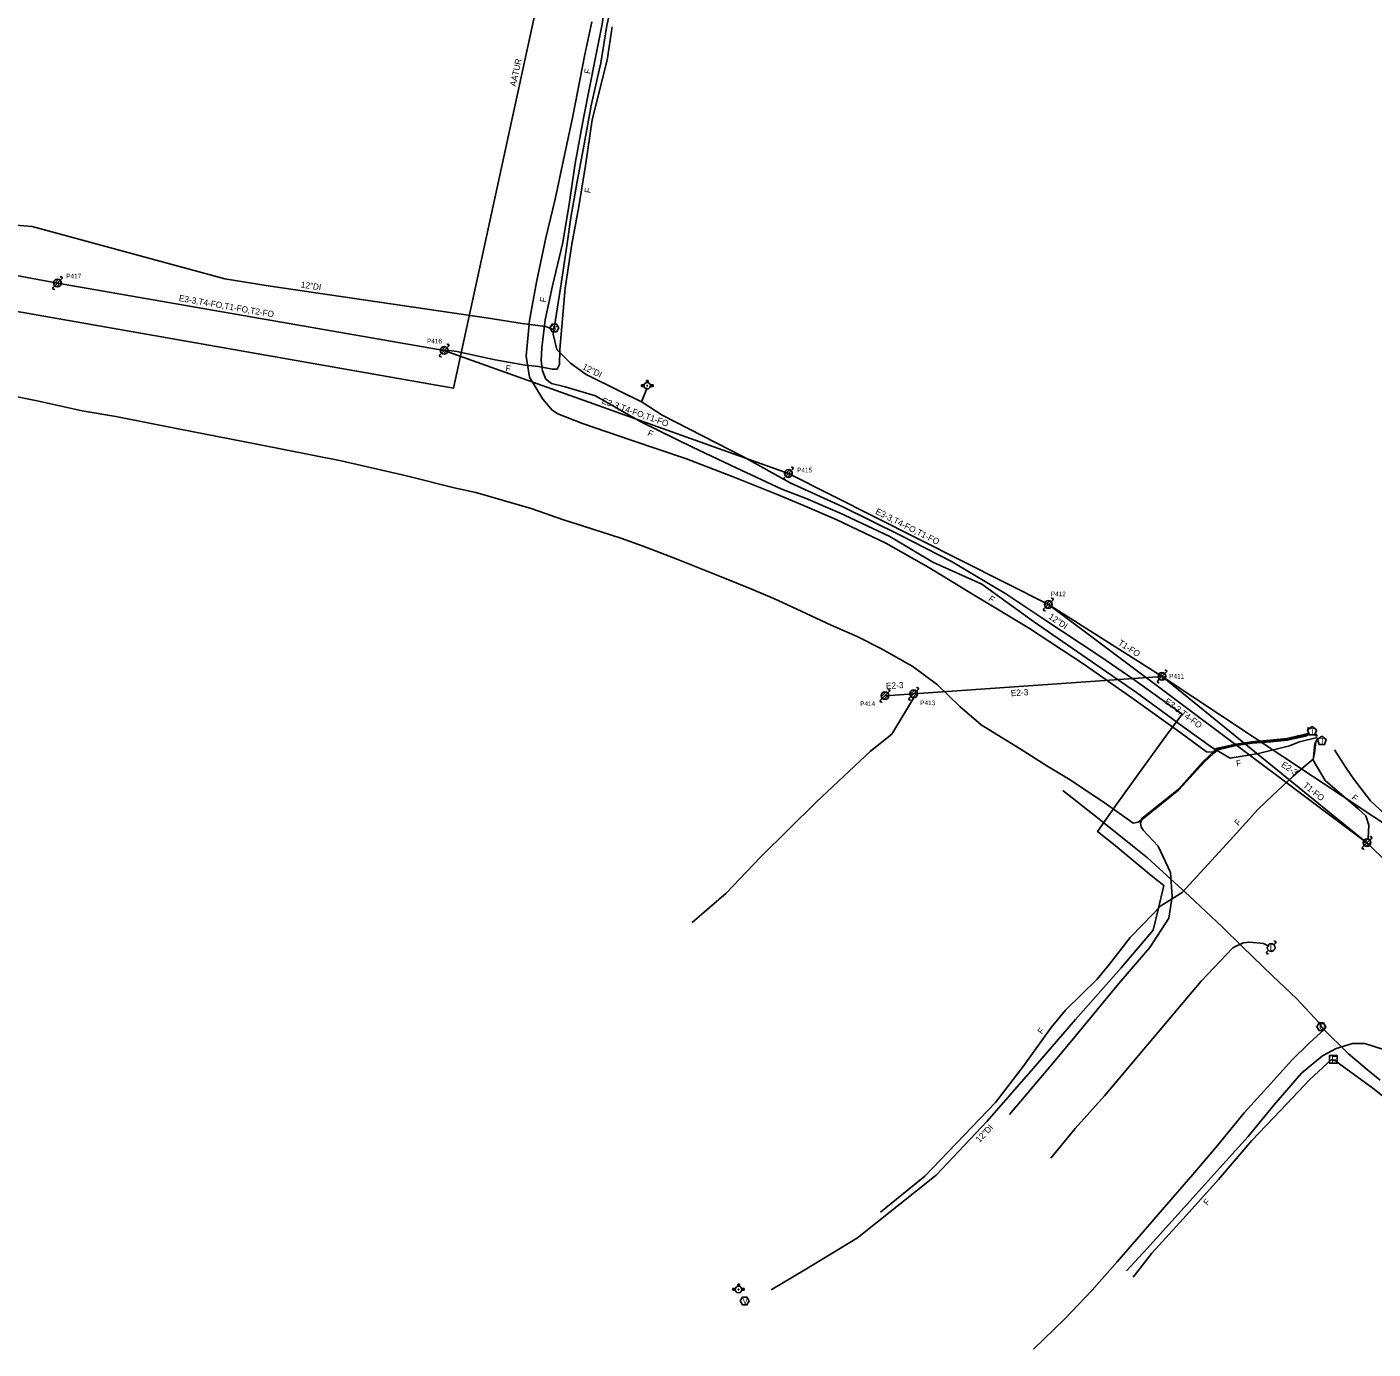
# Model space of a CAD drawing. Extents: x 1614474 to 1865144, y 1098877 to 1212550.
# Drawn here: x 1819688 to 1820556, y 1191145 to 1191998 of the extents above; entities that cross this region are included whole.
import ezdxf

# ---------------------------------------------------------------- set-up
doc = ezdxf.new("R2010")
doc.units = 0
for name, color, linetype in [('RD_EX_SU_Elec', 7, 'Continuous'), ('RD_EX_SU_Gas', 7, 'Continuous'), ('RD_EX_SU_H2O', 7, 'Continuous'), ('RD_EX_SU_Ovhd', 7, 'Continuous'), ('RD_EX_SU_Pole', 7, 'Continuous'), ('RD_EX_SU_Telecom', 7, 'Continuous'), ('RD_EX_SU_TX_H2O', 7, 'Continuous'), ('RD_EX_SU_TX_Pole', 7, 'Continuous'), ('RD_EX_SU_TX_Telecom', 7, 'Continuous')]:
    doc.layers.add(name, color=color, linetype=linetype)

# ---------------------------------------------------------------- blocks, each defined once
blk = doc.blocks.new('SUE_WV')
at = {"layer": 'RD_EX_SU_H2O'}
blk.add_lwpolyline([(2.89, 0), (1.44, 2.5), (-1.44, 2.5), (-2.89, 0), (-1.44, -2.5), (1.44, -2.5)], close=True, dxfattribs=at)
blk.add_text('V', height=3.75, dxfattribs=at).set_placement((-1.43, -1.88))
blk = doc.blocks.new('SUE_WFH')
at = {"layer": 'RD_EX_SU_H2O'}
for p, q in [((-2.01, 0.6), (-3.65, 0.6)), ((-3.65, 0.6), (-3.65, -0.45)), ((-0.48, 3.38), (-0.48, 2.04)), ((0.57, 3.38), (-0.48, 3.38)), ((0.57, 2.02), (0.57, 3.38)), ((3.7, 0.6), (2.01, 0.6)), ((3.7, -0.45), (3.7, 0.6)), ((-3.65, -0.45), (-2.05, -0.45)), ((2.05, -0.45), (3.7, -0.45))]:
    blk.add_line(p, q, dxfattribs=at)
for radius in [2.1, 0.263]:
    blk.add_circle((0, 0), radius, dxfattribs=at)
for start, end in [(163.3387, 192.31502), (74.24552, 103.21276), (347.68498, 16.6613)]:
    blk.add_arc((0, 0), 2.1, start, end, dxfattribs=at)
blk = doc.blocks.new('SUE_GVC')
at = {"layer": 'RD_EX_SU_Gas'}
blk.add_lwpolyline([(1.44, -2.5), (2.89, 0), (1.44, 2.5), (-1.44, 2.5), (-2.89, 0), (-1.44, -2.5)], close=True, dxfattribs=at)
blk.add_text('G', height=3.75, dxfattribs=at).set_placement((-1.34, -1.88))
blk = doc.blocks.new('SUE_PP')
at = {"layer": 'RD_EX_SU_Pole'}
for p, q in [((-2.41, -0.65), (0.65, 2.41)), ((-1.77, -1.77), (1.77, 1.77)), ((-0.65, -2.41), (2.41, 0.65)), ((1.77, 1.77), (2.83, 2.83)), ((-2.83, -2.83), (-1.77, -1.77))]:
    blk.add_line(p, q, dxfattribs=at)
blk.add_circle((0, 0), 2.5, dxfattribs=at)
for centre, start, end in [((2.3, 3.36), 315, 135), ((-2.3, -3.36), 135, 315)]:
    blk.add_arc(centre, 0.75, start, end, dxfattribs=at)

msp = doc.modelspace()

# ---------------------------------------------------------------- linework, layer by layer
at = {"layer": 'RD_EX_SU_Elec'}
for points in [[(1820117.23, 1191420.46), (1820139.16, 1191439.31), (1820161.2, 1191462.5), (1820197.42, 1191498.27), (1820232.28, 1191530.9), (1820245.99, 1191541.84), (1820260.6, 1191566.08)], [(1820531.48, 1191531.69), (1820539.33, 1191519.78), (1820543.95, 1191512.8), (1820554.72, 1191498.92), (1820566.71, 1191487.66), (1820596, 1191467.52), (1820611.35, 1191452.66)], [(1820348.6, 1191268.45), (1820364.31, 1191287.4), (1820383.23, 1191308.59), (1820445.62, 1191382.43), (1820465.97, 1191404.13), (1820472.71, 1191407.24), (1820476.96, 1191407.7), (1820485.75, 1191406.82), (1820489.35, 1191404.99)], [(1820397.44, 1191195.65), (1820410.78, 1191210.12), (1820430.67, 1191232.22), (1820453.54, 1191257.69), (1820475.8, 1191282.25), (1820492.44, 1191302.57), (1820510.32, 1191323.24), (1820523.78, 1191334.32), (1820532.63, 1191339.18), (1820543.19, 1191342.42), (1820551.02, 1191342.27), (1820563.15, 1191338.5)]]:
    msp.add_lwpolyline(points, dxfattribs=at)
at = {"layer": 'RD_EX_SU_Gas'}
for points in [[(1820356.38, 1191505.62), (1820378.54, 1191488.19), (1820401.21, 1191469.89), (1820410.93, 1191462.17), (1820423.3, 1191450.65), (1820438.07, 1191437.28), (1820459.18, 1191417.57), (1820472.14, 1191404.77), (1820491.57, 1191386.07), (1820507.34, 1191371.1), (1820521.32, 1191356.1), (1820522.41, 1191354.63), (1820522.99, 1191353.17), (1820524.24, 1191351.86), (1820540.44, 1191335.88), (1820552.74, 1191325.4), (1820560.89, 1191318.77)], [(1820337.37, 1191145.2), (1820357.64, 1191164.75), (1820375.15, 1191183.24), (1820391.38, 1191201.45), (1820406.75, 1191219.39), (1820421.97, 1191236.64), (1820440.08, 1191257.73), (1820456.04, 1191276.44), (1820473.33, 1191297.51), (1820490.48, 1191316.43), (1820503.99, 1191331.57), (1820515.23, 1191342.64), (1820524.79, 1191351.32)]]:
    msp.add_lwpolyline(points, dxfattribs=at)
at = {"layer": 'RD_EX_SU_H2O'}
msp.add_line((1820084.49, 1191756.32), (1820088.16, 1191765.33), dxfattribs=at)
for points in [[(1820036.51, 1191858.44), (1820038.88, 1191875.15), (1820042.84, 1191897.15), (1820047.53, 1191922.47), (1820051.99, 1191947.48), (1820058.18, 1191974.95), (1820062.15, 1191999.04), (1820067.98, 1192024.17), (1820071.51, 1192043.35), (1820077.48, 1192067.06), (1820084.61, 1192099.31), (1820091.86, 1192124.8), (1820100.41, 1192152.47), (1820104.82, 1192168.52), (1820107.91, 1192178.54)], [(1819147.33, 1191918.52), (1819544.16, 1191883.35), (1819570.61, 1191880.2), (1819605.16, 1191876.28), (1819691.46, 1191869.4), (1819815.73, 1191835.67), (1819843.7, 1191831.09), (1819985.82, 1191810.12), (1820007.46, 1191806.84)], [(1820036.51, 1191858.44), (1820032.74, 1191832.48), (1820028.36, 1191805.11), (1820027.56, 1191799.88), (1820029.89, 1191789.99), (1820038.66, 1191781.17), (1820048.91, 1191773.83), (1820071.03, 1191762.91), (1820084.99, 1191756.08), (1820097.9, 1191747.71), (1820149.94, 1191721.05)], [(1820007.46, 1191806.84), (1820022.65, 1191804.77), (1820028.04, 1191803.02)], [(1820149.94, 1191721.05), (1820180.51, 1191704), (1820213.96, 1191688.84), (1820251.31, 1191670.31), (1820284.92, 1191653.1), (1820319.56, 1191632.41)], [(1820168.21, 1191183.47), (1820189.95, 1191196.34), (1820223.8, 1191217), (1820274.56, 1191257.42), (1820307.56, 1191292.16), (1820337.07, 1191326.17), (1820364.43, 1191357.7), (1820393.91, 1191391.11), (1820414.48, 1191415.4), (1820417.89, 1191428.69), (1820421.41, 1191444.22), (1820413.31, 1191450.68), (1820390.01, 1191470.08), (1820378.66, 1191479.03), (1820391.29, 1191497.09), (1820406.78, 1191518.65), (1820423.16, 1191541.13), (1820433.19, 1191554.81), (1820401.46, 1191577.53), (1820380.81, 1191591.84), (1820342.7, 1191616.89), (1820319.56, 1191632.41)]]:
    msp.add_lwpolyline(points, dxfattribs=at)
at = {"layer": 'RD_EX_SU_Ovhd'}
for p, q in [((1819457.3, 1191879.55), (1819707.8, 1191832.9)), ((1819707.8, 1191832.9), (1819957.27, 1191789.42)), ((1819957.27, 1191789.42), (1820179.31, 1191710.02)), ((1820179.31, 1191710.02), (1820346.97, 1191625.54)), ((1820346.97, 1191625.54), (1820420.31, 1191579.15)), ((1820346.97, 1191625.54), (1820552.49, 1191471.84)), ((1820260.11, 1191567.92), (1820420.31, 1191579.15)), ((1820420.31, 1191579.15), (1820611.99, 1191452.04)), ((1820420.31, 1191579.15), (1820552.49, 1191471.84)), ((1820241.59, 1191566.68), (1820260.11, 1191567.92)), ((1820552.49, 1191471.84), (1820734.07, 1191296.93))]:
    msp.add_line(p, q, dxfattribs=at)
at = {"layer": 'RD_EX_SU_Pole'}
for p, q in [((1819705.38, 1191832.25), (1819708.44, 1191835.31)), ((1819706.03, 1191831.13), (1819709.57, 1191834.66)), ((1819707.15, 1191830.48), (1819710.21, 1191833.54)), ((1819709.57, 1191834.66), (1819710.63, 1191835.72)), ((1819704.97, 1191830.07), (1819706.03, 1191831.13)), ((1819954.86, 1191788.78), (1819957.92, 1191791.84)), ((1819955.51, 1191787.66), (1819959.04, 1191791.19)), ((1819956.63, 1191787.01), (1819959.69, 1191790.07)), ((1819959.04, 1191791.19), (1819960.1, 1191792.25)), ((1819954.45, 1191786.6), (1819955.51, 1191787.66)), ((1820176.9, 1191709.37), (1820179.96, 1191712.43)), ((1820177.54, 1191708.25), (1820181.08, 1191711.78)), ((1820181.08, 1191711.78), (1820182.14, 1191712.85)), ((1820176.48, 1191707.19), (1820177.54, 1191708.25)), ((1820178.66, 1191707.6), (1820181.73, 1191710.66)), ((1820344.56, 1191624.89), (1820347.62, 1191627.96)), ((1820345.2, 1191623.77), (1820348.74, 1191627.31)), ((1820346.32, 1191623.13), (1820349.39, 1191626.19)), ((1820348.74, 1191627.31), (1820349.8, 1191628.37)), ((1820344.14, 1191622.71), (1820345.2, 1191623.77)), ((1820487.84, 1191401.39), (1820488.9, 1191402.45)), ((1820492.44, 1191405.99), (1820493.5, 1191407.05))]:
    msp.add_line(p, q, dxfattribs=at)
for centre in [(1819707.8, 1191832.9), (1819957.27, 1191789.42), (1820179.31, 1191710.02), (1820346.97, 1191625.54), (1820490.67, 1191404.22)]:
    msp.add_circle(centre, 2.5, dxfattribs=at)
for centre, start, end in [((1819710.1, 1191836.25), 315, 135), ((1819705.5, 1191829.54), 135, 315), ((1819959.57, 1191792.78), 315, 135), ((1819954.98, 1191786.07), 135, 315), ((1820181.61, 1191713.38), 315, 135), ((1820177.01, 1191706.66), 135, 315), ((1820349.27, 1191628.9), 315, 135), ((1820344.67, 1191622.18), 135, 315), ((1820492.97, 1191407.58), 315, 135), ((1820488.37, 1191400.86), 135, 315)]:
    msp.add_arc(centre, 0.75, start, end, dxfattribs=at)
at = {"layer": 'RD_EX_SU_Telecom'}
for p, q in [((1820515.43, 1191545.4), (1820514.02, 1191546.18)), ((1820520.17, 1191540.43), (1820518.6, 1191542.22)), ((1820520.58, 1191541.05), (1820518.99, 1191542.6))]:
    msp.add_line(p, q, dxfattribs=at)
for points in [[(1820020.74, 1191776.2), (1820019.8, 1191782.68), (1820020.22, 1191791.05), (1820022.34, 1191809.12), (1820027.11, 1191831.03), (1820033.7, 1191858.96), (1820037.9, 1191883.86), (1820041.76, 1191910.02), (1820047.2, 1191939.2), (1820054.87, 1191978.46), (1820059.17, 1191999.94), (1820062.87, 1192025.73), (1820073.1, 1192071.26), (1820081.89, 1192097.42), (1820088.82, 1192119.73), (1820093.94, 1192134.6), (1820093.61, 1192137.35)], [(1819273.38, 1191837.73), (1819283.19, 1191836.01), (1819404.71, 1191814.63), (1819438.76, 1191858.18), (1819652.24, 1191819.72), (1819963.17, 1191765.03), (1820039.32, 1192115.22)], [(1819958.67, 1191789.48), (1819965.36, 1191788.65), (1819990.11, 1191783.39), (1820009.52, 1191779.93), (1820017.99, 1191779.05), (1820027.08, 1191777.25), (1820030.13, 1191777.34), (1820031.66, 1191780.35), (1820031.76, 1191790.12), (1820035.32, 1191829.6), (1820039.63, 1191857.97), (1820044.11, 1191882.32), (1820048.45, 1191908.69), (1820052.7, 1191938.14), (1820062.38, 1191976.64), (1820065.5, 1191998.17)], [(1820052.52, 1192001.38), (1820047.98, 1191980.33), (1820040.32, 1191940.51), (1820034.15, 1191912.36), (1820028.82, 1191886.96), (1820022.84, 1191862.03), (1820016.86, 1191833.55), (1820012.35, 1191808.75), (1820010.12, 1191785.81), (1820012.35, 1191772.27), (1820020.8, 1191757.93), (1820026.83, 1191750.92), (1820030.64, 1191748.54), (1820046.44, 1191742.31), (1820077.94, 1191731.42), (1820113.63, 1191719.54), (1820143.66, 1191707.77), (1820171.58, 1191696.66), (1820188.52, 1191689.49), (1820210, 1191680.26), (1820242.07, 1191664.99), (1820269.85, 1191649.36), (1820299.09, 1191631.62), (1820334.25, 1191610.38), (1820369.19, 1191587.42), (1820400.75, 1191565.28), (1820431.84, 1191543.08), (1820449.03, 1191530.43), (1820453.13, 1191530.22), (1820455.98, 1191532.12), (1820467.77, 1191534.98), (1820478.15, 1191536.64), (1820490.18, 1191537.63), (1820501.2, 1191538.42), (1820508.29, 1191540.19), (1820512.2, 1191541.13), (1820515.79, 1191541.49)], [(1820020.74, 1191776.2), (1820022.71, 1191770.94), (1820026.37, 1191767.99), (1820035.29, 1191765.91), (1820054.91, 1191760.12), (1820084.1, 1191743.35), (1820117.42, 1191727.04), (1820145.61, 1191713.71), (1820175.13, 1191699.84), (1820190.65, 1191693.83), (1820212.32, 1191684.58), (1820244.72, 1191669.28), (1820272.34, 1191652.9), (1820304, 1191638.56), (1820337.46, 1191614.55), (1820371.94, 1191590.6), (1820403.73, 1191568.67), (1820434.6, 1191546.1), (1820452.9, 1191533.04), (1820464.31, 1191526.31), (1820482.47, 1191529.49), (1820502.47, 1191534.41), (1820508.98, 1191537.02), (1820520.46, 1191539.72)], [(1819660.43, 1191763.87), (1819694.61, 1191757), (1819723.82, 1191750.41), (1819745.33, 1191746.78), (1819785.74, 1191738.86), (1819836.47, 1191728.92), (1819890.68, 1191718.19), (1819932.98, 1191708.44), (1819963.61, 1191700.84), (1819977.57, 1191697.72), (1820013.32, 1191687.36), (1820034.25, 1191680.18), (1820047.2, 1191676.14), (1820071.22, 1191668.31), (1820085.62, 1191663.05), (1820107.91, 1191654.46), (1820138.02, 1191642.53), (1820154.97, 1191635.7), (1820169.94, 1191629.34), (1820187.52, 1191621.32), (1820206.84, 1191612.24), (1820223.58, 1191604.85), (1820239.3, 1191596.93), (1820259.59, 1191585.43), (1820275.52, 1191573.64), (1820289.75, 1191559.63), (1820303.72, 1191547.89), (1820316.47, 1191540.02), (1820328.82, 1191532.49), (1820346.06, 1191521.42), (1820360.98, 1191512.34), (1820384.54, 1191496.63), (1820397.71, 1191487.24), (1820401.7, 1191484.54), (1820404.85, 1191485.1), (1820407.62, 1191487.09), (1820431.12, 1191505.96), (1820447.36, 1191523.8), (1820453.79, 1191529.53), (1820456.32, 1191531.7), (1820467.89, 1191534.55), (1820478.36, 1191536.17), (1820490.4, 1191536.86), (1820501.23, 1191538.05), (1820508.84, 1191539.7), (1820512.73, 1191540.48), (1820515.71, 1191542.39)], [(1820238.66, 1191233.45), (1820267.28, 1191256.68), (1820312.78, 1191304.24), (1820330.7, 1191327.52), (1820348.67, 1191352.59), (1820358.07, 1191363.8), (1820378.51, 1191383.93), (1820386.44, 1191393.42), (1820399.66, 1191410.8), (1820407.85, 1191419.06), (1820419.53, 1191431.12), (1820433.26, 1191439.81), (1820457.16, 1191465.69), (1820466.35, 1191475.93), (1820482.26, 1191493.4), (1820491.49, 1191502.37), (1820504.62, 1191514.58), (1820511.38, 1191520.35), (1820517.86, 1191525.75), (1820518.74, 1191529.64), (1820519.45, 1191536.87), (1820520.97, 1191539.38)], [(1820321.86, 1191296.54), (1820349.08, 1191328.64), (1820362.02, 1191344.28), (1820375.13, 1191360.15), (1820392.5, 1191381.01), (1820412.42, 1191404.19), (1820424.71, 1191423.27), (1820426.91, 1191437.06), (1820425.78, 1191452.64), (1820417.72, 1191469.72), (1820408.02, 1191480), (1820406.75, 1191482.1), (1820406.36, 1191484.51), (1820407.15, 1191487.46), (1820430.84, 1191506.36), (1820446.77, 1191524.27), (1820454.01, 1191531), (1820455.24, 1191532.59), (1820467.85, 1191535.42), (1820478.17, 1191537.02), (1820490.11, 1191537.99), (1820501.02, 1191539.06), (1820508.02, 1191540.9), (1820512.16, 1191541.59), (1820514.57, 1191542.37)], [(1820520.54, 1191538.8), (1820518.75, 1191535.73), (1820517.8, 1191525), (1820525.47, 1191511.91), (1820546.73, 1191493.75), (1820551.66, 1191489.29), (1820551.74, 1191489.21), (1820553.72, 1191483.12), (1820553.33, 1191474.7)], [(1820401.64, 1191191.64), (1820413.7, 1191207.1), (1820433.83, 1191229.18), (1820456.81, 1191254.54), (1820478.18, 1191279.82), (1820496.67, 1191299.09), (1820515.59, 1191319.16), (1820529.42, 1191331.83), (1820532.45, 1191331.17), (1820534.97, 1191328.91), (1820548.22, 1191319.22), (1820556.16, 1191313.41), (1820569.93, 1191302.49)]]:
    msp.add_lwpolyline(points, dxfattribs=at)
for points in [[(1820517.03, 1191546.79), (1820514.17, 1191544.72), (1820515.26, 1191541.36), (1820518.79, 1191541.36), (1820519.88, 1191544.72)], [(1820523.36, 1191540.55), (1820520.51, 1191538.47), (1820521.6, 1191535.12), (1820525.12, 1191535.12), (1820526.21, 1191538.47)], [(1820533.32, 1191334.53), (1820528.32, 1191334.53), (1820528.32, 1191329.53), (1820533.32, 1191329.53)]]:
    msp.add_lwpolyline(points, close=True, dxfattribs=at)

# ---------------------------------------------------------------- block references
at = {"layer": 'RD_EX_SU_Gas'}
msp.add_blockref('SUE_GVC', (1820522.99, 1191353.17), dxfattribs=at)
at = {"layer": 'RD_EX_SU_H2O'}
for name, p in [('SUE_WV', (1820028.27, 1191803.96)), ('SUE_WFH', (1820088.25, 1191766.67)), ('SUE_WFH', (1820147.09, 1191183.66)), ('SUE_WV', (1820151.12, 1191176.23))]:
    msp.add_blockref(name, p, dxfattribs=at)
at = {"layer": 'RD_EX_SU_Pole'}
for p in [(1820420.31, 1191579.15), (1820241.59, 1191566.68), (1820260.11, 1191567.92), (1820552.49, 1191471.84)]:
    msp.add_blockref('SUE_PP', p, dxfattribs=at)

# ---------------------------------------------------------------- texts
at = {"layer": 'RD_EX_SU_Ovhd'}
for s, rotation, p in [('E3-3,T4-FO,T1-FO,T2-FO', 350.11537, (1819785.87, 1191821.32)), ('E3-3,T4-FO,T1-FO', 340.32152, (1820058.56, 1191755.32)), ('E3-3,T4-FO,T1-FO', 333.25858, (1820235.03, 1191684.18)), ('T1-FO', 327.68337, (1820391.55, 1191599.71)), ('E2-3', 3.80368, (1820242.35, 1191570.91)), ('E2-3', 4.01198, (1820322.89, 1191566.3)), ('E3-3,T4-FO', 323.20863, (1820421.58, 1191562.25)), ('E2-3', 326.44946, (1820496.77, 1191521.24)), ('T1-FO', 320.92973, (1820510.94, 1191508.15))]:
    msp.add_text(s, height=4, rotation=rotation, dxfattribs=at).set_placement(p)
at = {"layer": 'RD_EX_SU_Pole'}
msp.add_text('L', height=4, dxfattribs=at).set_placement((1820489.81, 1191402.22))
at = {"layer": 'RD_EX_SU_Telecom'}
for s, height, p in [('T', 3.75, (1820515.77, 1191541.92)), ('T', 3.75, (1820522.1, 1191535.67)), ('F', 4, (1820529.58, 1191330.03))]:
    msp.add_text(s, height=height, dxfattribs=at).set_placement(p)
msp.add_text('F', height=4, rotation=47.68244, dxfattribs=at).set_placement((1820469.55, 1191482.42))
at = {"layer": 'RD_EX_SU_TX_H2O'}
for rotation, p in [(351.60695, (1819864.56, 1191830.04)), (333.73184, (1820045.96, 1191777.51)), (326.67758, (1820346.69, 1191616.66)), (46.47426, (1820302.57, 1191278.2))]:
    msp.add_text('12"DI', height=4, rotation=rotation, dxfattribs=at).set_placement(p)
at = {"layer": 'RD_EX_SU_TX_Pole'}
for s, p in [('P417', (1819713.44, 1191835.85)), ('P416', (1819946.14, 1191793.98)), ('P415', (1820184.89, 1191710.73)), ('P412', (1820348.54, 1191630.85)), ('P411', (1820424.92, 1191577.76)), ('P414', (1820225.54, 1191559.99)), ('P413', (1820264.3, 1191560.58))]:
    msp.add_text(s, height=3, dxfattribs=at).set_placement(p)
at = {"layer": 'RD_EX_SU_TX_Telecom'}
for s, rotation, p in [('AATUR', 77.73212, (1820003.4, 1191959.44)), ('F', 78.9437, (1820051.38, 1191967.53)), ('F', 80.65996, (1820051.56, 1191890.66)), ('F', 77.73913, (1820022.68, 1191820.07)), ('F', 349.8742, (1819996.51, 1191776.15)), ('F', 333.91983, (1820088.01, 1191734.76)), ('F', 324.3331, (1820307.91, 1191628.37)), ('F', 9.92502, (1820468.48, 1191520.95)), ('F', 319.49764, (1820542.11, 1191500.33)), ('F', 54.36076, (1820342.86, 1191347.92)), ('F', 47.81753, (1820449.48, 1191237.51))]:
    msp.add_text(s, height=4, rotation=rotation, dxfattribs=at).set_placement(p)

doc.saveas('drawing.dxf')
